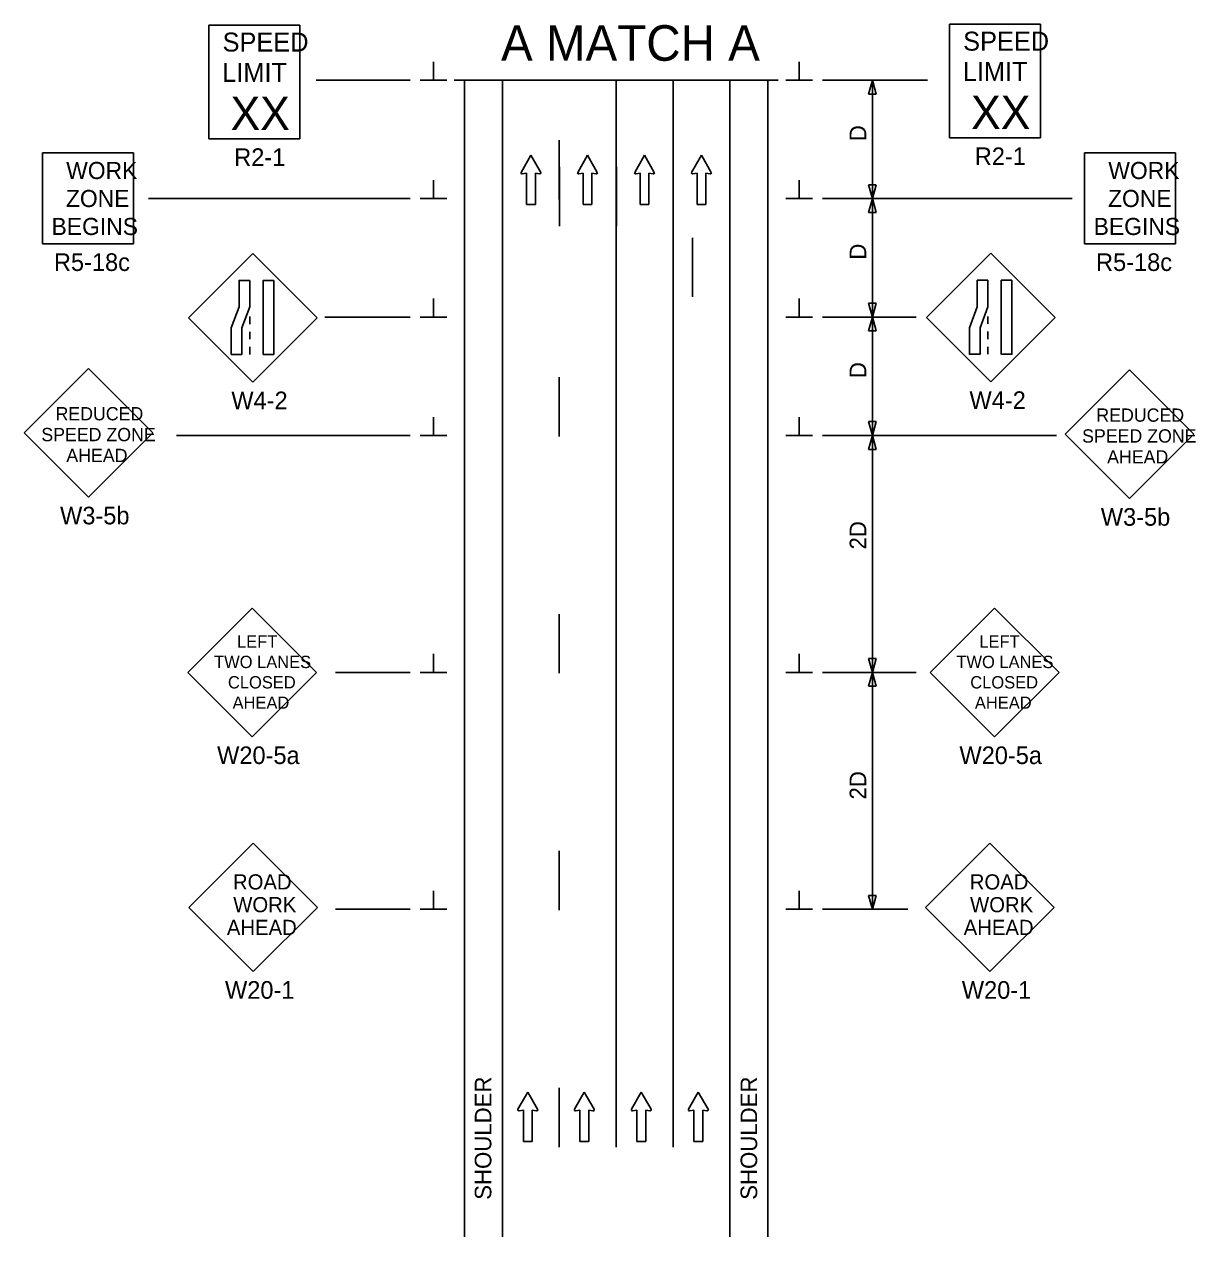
# Model space of a CAD drawing. Extents: x 16512 to 19504, y 5761 to 6984.
# Drawn here: x 17851 to 18346, y 6401 to 6913 of the extents above; entities that cross this region are included whole.
import ezdxf

# ---------------------------------------------------------------- set-up
doc = ezdxf.new("R2010")
doc.units = 0
for name, color, linetype in [('ALI_LEGAL_EX', 7, 'Continuous'), ('MT_SCRATCH_LEVEL_E', 7, 'Continuous'), ('PAVT_EDGE_EX', 7, 'Continuous'), ('TRAFFIC_SIGNS_PR', 7, 'Continuous'), ('TYPICAL_TEXT_DIMEN_PR', 7, 'Continuous')]:
    doc.layers.add(name, color=color, linetype=linetype)

msp = doc.modelspace()

# ---------------------------------------------------------------- linework, layer by layer
at = {"layer": 'ALI_LEGAL_EX'}
for p, q in [((18101.18, 6438.7), (18101.18, 6889.05)), ((18125.18, 6438.7), (18125.18, 6889.05))]:
    msp.add_line(p, q, dxfattribs=at)
for points in [[(18077.18, 6838.7), (18077.18, 6863.7)], [(18101.18, 6838.7), (18101.18, 6863.7)], [(18125.18, 6838.7), (18125.18, 6863.7)], [(18077.28, 6852.4), (18077.28, 6827.4)], [(18101.28, 6852.4), (18101.28, 6827.4)], [(18133.42, 6822.52), (18133.42, 6797.52)], [(18077.18, 6738.7), (18077.18, 6763.7)], [(18101.18, 6738.7), (18101.18, 6763.7)], [(18125.18, 6738.7), (18125.18, 6763.7)], [(18077.18, 6638.7), (18077.18, 6663.7)], [(18101.18, 6638.7), (18101.18, 6663.7)], [(18125.18, 6638.7), (18125.18, 6663.7)], [(18077.18, 6538.7), (18077.18, 6563.7)], [(18101.18, 6538.7), (18101.18, 6563.7)], [(18125.18, 6538.7), (18125.18, 6563.7)], [(18077.18, 6438.7), (18077.18, 6463.7)], [(18101.18, 6438.7), (18101.18, 6463.7)], [(18125.18, 6438.7), (18125.18, 6463.7)]]:
    msp.add_lwpolyline(points, dxfattribs=at)
at = {"layer": 'MT_SCRATCH_LEVEL_E'}
for p, q in [((18065.19, 6857.36), (18061.08, 6850.12)), ((18069.34, 6850.12), (18065.19, 6857.36)), ((18089.05, 6857.36), (18084.94, 6850.12)), ((18093.19, 6850.12), (18089.05, 6857.36)), ((18113.1, 6857.36), (18108.99, 6850.12)), ((18117.25, 6850.12), (18113.1, 6857.36)), ((18137.15, 6857.36), (18133.04, 6850.12)), ((18137.15, 6857.36), (18133.04, 6850.12)), ((18141.3, 6850.12), (18137.15, 6857.36)), ((18141.3, 6850.12), (18137.15, 6857.36)), ((18061.57, 6849.44), (18063.34, 6849.75)), ((18063.34, 6849.75), (18063.34, 6836.5)), ((18067.08, 6836.5), (18067.08, 6849.75)), ((18067.08, 6849.75), (18068.86, 6849.44)), ((18085.42, 6849.44), (18087.19, 6849.75)), ((18087.19, 6849.75), (18087.19, 6836.5)), ((18090.94, 6836.5), (18090.94, 6849.75)), ((18090.94, 6849.75), (18092.71, 6849.44)), ((18109.47, 6849.44), (18111.25, 6849.75)), ((18111.25, 6849.75), (18111.25, 6836.5)), ((18114.99, 6836.5), (18114.99, 6849.75)), ((18114.99, 6849.75), (18116.77, 6849.44)), ((18133.52, 6849.44), (18135.3, 6849.76)), ((18133.52, 6849.44), (18135.3, 6849.76)), ((18135.3, 6849.76), (18135.3, 6836.5)), ((18135.3, 6849.76), (18135.3, 6836.5)), ((18139.04, 6836.5), (18139.04, 6849.76)), ((18139.04, 6849.76), (18140.82, 6849.44)), ((18139.04, 6836.5), (18139.04, 6849.76)), ((18139.04, 6849.76), (18140.82, 6849.44)), ((18063.34, 6836.5), (18067.08, 6836.5)), ((18087.19, 6836.5), (18090.94, 6836.5)), ((18111.25, 6836.5), (18114.99, 6836.5)), ((18135.3, 6836.5), (18139.04, 6836.5)), ((18135.3, 6836.5), (18139.04, 6836.5)), ((18063.86, 6461.9), (18059.75, 6454.66)), ((18068, 6454.66), (18063.86, 6461.9)), ((18087.71, 6461.9), (18083.6, 6454.66)), ((18091.86, 6454.66), (18087.71, 6461.9)), ((18111.76, 6461.9), (18107.65, 6454.66)), ((18115.91, 6454.66), (18111.76, 6461.9)), ((18135.81, 6461.9), (18131.7, 6454.66)), ((18135.81, 6461.9), (18131.7, 6454.66)), ((18139.96, 6454.66), (18135.81, 6461.9)), ((18139.96, 6454.66), (18135.81, 6461.9)), ((18060.23, 6453.98), (18062.01, 6454.29)), ((18062.01, 6454.29), (18062.01, 6441.04)), ((18065.75, 6441.04), (18065.75, 6454.29)), ((18065.75, 6454.29), (18067.52, 6453.98)), ((18084.08, 6453.98), (18085.86, 6454.29)), ((18085.86, 6454.29), (18085.86, 6441.04)), ((18089.6, 6441.04), (18089.6, 6454.29)), ((18089.6, 6454.29), (18091.38, 6453.98)), ((18108.13, 6453.98), (18109.91, 6454.29)), ((18109.91, 6454.29), (18109.91, 6441.04)), ((18113.65, 6441.04), (18113.65, 6454.29)), ((18113.65, 6454.29), (18115.43, 6453.98)), ((18132.19, 6453.98), (18133.96, 6454.29)), ((18132.19, 6453.98), (18133.96, 6454.29)), ((18133.96, 6454.29), (18133.96, 6441.04)), ((18133.96, 6454.29), (18133.96, 6441.04)), ((18137.7, 6441.04), (18137.7, 6454.29)), ((18137.7, 6454.29), (18139.48, 6453.98)), ((18137.7, 6441.04), (18137.7, 6454.29)), ((18137.7, 6454.29), (18139.48, 6453.98)), ((18062.01, 6441.04), (18065.75, 6441.04)), ((18085.86, 6441.04), (18089.6, 6441.04)), ((18109.91, 6441.04), (18113.65, 6441.04)), ((18133.96, 6441.04), (18137.7, 6441.04)), ((18133.96, 6441.04), (18137.7, 6441.04))]:
    msp.add_line(p, q, dxfattribs=at)
for centre, start, end in [((18061.49, 6849.9), 150.4248, 279.9638), ((18068.93, 6849.9), 260.0362, 29.7731), ((18085.34, 6849.9), 150.4248, 279.9638), ((18092.78, 6849.9), 260.0362, 29.7731), ((18109.4, 6849.9), 150.4248, 279.9638), ((18116.84, 6849.9), 260.0362, 29.7731), ((18133.45, 6849.9), 150.4248, 279.9638), ((18133.45, 6849.9), 150.4248, 279.9638), ((18140.89, 6849.9), 260.0362, 29.7731), ((18140.89, 6849.9), 260.0362, 29.7731), ((18060.15, 6454.44), 150.4248, 279.9638), ((18067.6, 6454.44), 260.0362, 29.7731), ((18084.01, 6454.44), 150.4248, 279.9638), ((18091.45, 6454.44), 260.0362, 29.7731), ((18108.06, 6454.44), 150.4248, 279.9638), ((18115.5, 6454.44), 260.0362, 29.7731), ((18132.11, 6454.44), 150.4248, 279.9638), ((18132.11, 6454.44), 150.4248, 279.9638), ((18139.55, 6454.44), 260.0362, 29.7731), ((18139.55, 6454.44), 260.0362, 29.7731)]:
    msp.add_arc(centre, 0.463, start, end, dxfattribs=at)
at = {"layer": 'PAVT_EDGE_EX'}
for p, q in [((18037.18, 6889.05), (18037.18, 6400.84)), ((18053.18, 6889.05), (18053.18, 6400.84)), ((18149.18, 6889.05), (18149.18, 6400.84)), ((18165.18, 6889.05), (18165.18, 6400.84))]:
    msp.add_line(p, q, dxfattribs=at)
at = {"layer": 'TRAFFIC_SIGNS_PR'}
for p, q in [((17929.34, 6912.26), (17967.74, 6912.26)), ((17929.34, 6864.26), (17929.34, 6912.26)), ((17967.74, 6864.26), (17967.74, 6912.26)), ((18241.83, 6912.64), (18280.23, 6912.64)), ((18241.83, 6864.64), (18241.83, 6912.64)), ((18280.23, 6864.64), (18280.23, 6912.64)), ((17929.34, 6864.26), (17967.74, 6864.26)), ((18241.83, 6864.64), (18280.23, 6864.64)), ((17859.12, 6819.94), (17859.12, 6858.34)), ((17859.12, 6858.34), (17897.52, 6858.34)), ((17897.52, 6819.94), (17897.52, 6858.34)), ((18298.86, 6819.94), (18298.86, 6858.34)), ((18298.86, 6858.34), (18337.26, 6858.34)), ((18337.26, 6819.94), (18337.26, 6858.34)), ((17859.12, 6819.94), (17897.52, 6819.94)), ((18298.86, 6819.94), (18337.26, 6819.94)), ((17947.84, 6815.91), (17920.68, 6788.76)), ((17974.99, 6788.76), (17947.84, 6815.91)), ((18259.31, 6815.98), (18232.16, 6788.83)), ((18286.47, 6788.83), (18259.31, 6815.98)), ((17920.68, 6788.76), (17947.84, 6761.6)), ((17946.59, 6789.25), (17946.59, 6786.05)), ((17947.84, 6761.6), (17974.99, 6788.76)), ((18232.16, 6788.83), (18259.31, 6761.68)), ((18258.07, 6789.32), (18258.07, 6786.12)), ((18259.31, 6761.68), (18286.47, 6788.83)), ((17946.59, 6782.85), (17946.59, 6779.65)), ((18258.07, 6782.92), (18258.07, 6779.72)), ((17946.59, 6776.45), (17946.59, 6773.25)), ((18258.07, 6776.52), (18258.07, 6773.32)), ((17878.56, 6767.3), (17851.41, 6740.15)), ((17905.72, 6740.15), (17878.56, 6767.3)), ((18317.75, 6766.71), (18290.6, 6739.55)), ((18344.91, 6739.55), (18317.75, 6766.71)), ((17851.41, 6740.15), (17878.56, 6712.99)), ((17878.56, 6712.99), (17905.72, 6740.15)), ((18290.6, 6739.55), (18317.75, 6712.4)), ((18317.75, 6712.4), (18344.91, 6739.55)), ((17947.65, 6666.1), (17920.5, 6638.95)), ((17974.8, 6638.95), (17947.65, 6666.1)), ((18260.89, 6666.1), (18233.74, 6638.95)), ((18288.05, 6638.95), (18260.89, 6666.1)), ((17920.5, 6638.95), (17947.65, 6611.8)), ((17947.65, 6611.8), (17974.8, 6638.95)), ((18233.74, 6638.95), (18260.89, 6611.8)), ((18260.89, 6611.8), (18288.05, 6638.95)), ((17947.95, 6567.04), (17920.8, 6539.89)), ((17975.1, 6539.89), (17947.95, 6567.04)), ((18258.87, 6567.04), (18231.72, 6539.89)), ((18286.02, 6539.89), (18258.87, 6567.04)), ((17920.8, 6539.89), (17947.95, 6512.74)), ((17947.95, 6512.74), (17975.1, 6539.89)), ((18231.72, 6539.89), (18258.87, 6512.74)), ((18258.87, 6512.74), (18286.02, 6539.89))]:
    msp.add_line(p, q, dxfattribs=at)
for points in [[(17946.59, 6804.49), (17946.59, 6793.31), (17943.24, 6784.43), (17943.24, 6773.25), (17938.75, 6773.25), (17938.75, 6784.43), (17942.09, 6793.31), (17942.09, 6804.49)], [(17956.72, 6804.49), (17956.72, 6773.25), (17952.23, 6773.25), (17952.23, 6804.49)], [(18258.07, 6804.57), (18258.07, 6793.38), (18254.72, 6784.5), (18254.72, 6773.32), (18250.23, 6773.32), (18250.23, 6784.5), (18253.57, 6793.38), (18253.57, 6804.57)], [(18268.2, 6804.57), (18268.2, 6773.32), (18263.71, 6773.32), (18263.71, 6804.57)]]:
    msp.add_lwpolyline(points, close=True, dxfattribs=at)
at = {"layer": 'TYPICAL_TEXT_DIMEN_PR'}
for p, q in [((18024.15, 6889.05), (18024.15, 6896.83)), ((18178.4, 6889.05), (18178.4, 6896.83)), ((17974.63, 6889.05), (18014.28, 6889.05)), ((18018.53, 6889.05), (18029.78, 6889.05)), ((18032.85, 6889.05), (18169.5, 6889.05)), ((18184.03, 6889.05), (18172.78, 6889.05)), ((18188.28, 6889.05), (18232.62, 6889.05)), ((18207.71, 6883.19), (18209.28, 6889.05)), ((18209.28, 6889.05), (18209.28, 6839.05)), ((18209.28, 6889.05), (18210.85, 6883.19)), ((18209.28, 6883.19), (18207.71, 6883.19)), ((18210.85, 6883.19), (18209.28, 6883.19)), ((18024.15, 6839.05), (18024.15, 6846.83)), ((18178.4, 6839.05), (18178.4, 6846.83)), ((18209.28, 6839.05), (18207.71, 6844.91)), ((18207.71, 6844.91), (18209.28, 6844.91)), ((18209.28, 6844.91), (18210.85, 6844.91)), ((18210.85, 6844.91), (18209.28, 6839.05)), ((18014.28, 6839.05), (17903.81, 6839.05)), ((18018.53, 6839.05), (18029.78, 6839.05)), ((18184.03, 6839.05), (18172.78, 6839.05)), ((18188.28, 6839.05), (18293.55, 6839.05)), ((18207.71, 6833.19), (18209.28, 6839.05)), ((18209.28, 6839.05), (18210.85, 6833.19)), ((18209.28, 6839.05), (18209.28, 6789.05)), ((18209.28, 6833.19), (18207.71, 6833.19)), ((18210.85, 6833.19), (18209.28, 6833.19)), ((18024.15, 6789.05), (18024.15, 6796.83)), ((18178.4, 6789.05), (18178.4, 6796.83)), ((18209.28, 6789.05), (18207.71, 6794.91)), ((18207.71, 6794.91), (18209.28, 6794.91)), ((18209.28, 6794.91), (18210.85, 6794.91)), ((18210.85, 6794.91), (18209.28, 6789.05)), ((18014.28, 6789.05), (17978.28, 6789.05)), ((18018.53, 6789.05), (18029.78, 6789.05)), ((18184.03, 6789.05), (18172.78, 6789.05)), ((18188.28, 6789.05), (18227.73, 6789.05)), ((18207.71, 6783.19), (18209.28, 6789.05)), ((18209.28, 6789.05), (18209.28, 6739.05)), ((18209.28, 6789.05), (18210.85, 6783.19)), ((18209.28, 6783.19), (18207.71, 6783.19)), ((18210.85, 6783.19), (18209.28, 6783.19)), ((18024.15, 6739.05), (18024.15, 6746.83)), ((18178.4, 6739.05), (18178.4, 6746.83)), ((18209.28, 6739.05), (18207.71, 6744.91)), ((18207.71, 6744.91), (18209.28, 6744.91)), ((18209.28, 6744.91), (18210.85, 6744.91)), ((18210.85, 6744.91), (18209.28, 6739.05)), ((17915.6, 6739.05), (18014.28, 6739.05)), ((18018.53, 6739.05), (18029.78, 6739.05)), ((18184.03, 6739.05), (18172.78, 6739.05)), ((18188.28, 6739.05), (18286.96, 6739.05)), ((18207.71, 6733.19), (18209.28, 6739.05)), ((18207.71, 6733.19), (18209.28, 6739.05)), ((18209.28, 6739.05), (18209.28, 6639.05)), ((18209.28, 6739.05), (18210.85, 6733.19)), ((18209.28, 6739.05), (18210.85, 6733.19)), ((18209.28, 6739.05), (18209.28, 6639.05)), ((18209.28, 6733.19), (18207.71, 6733.19)), ((18209.28, 6733.19), (18207.71, 6733.19)), ((18210.85, 6733.19), (18209.28, 6733.19)), ((18210.85, 6733.19), (18209.28, 6733.19)), ((18024.15, 6639.05), (18024.15, 6646.83)), ((18024.15, 6639.05), (18024.15, 6646.83)), ((18178.4, 6639.05), (18178.4, 6646.83)), ((18178.4, 6639.05), (18178.4, 6646.83)), ((18209.28, 6639.05), (18207.71, 6644.91)), ((18207.71, 6644.91), (18209.28, 6644.91)), ((18209.28, 6644.91), (18210.85, 6644.91)), ((18210.85, 6644.91), (18209.28, 6639.05)), ((17982.71, 6639.05), (18014.28, 6639.05)), ((18029.78, 6639.05), (18018.53, 6639.05)), ((18029.78, 6639.05), (18018.53, 6639.05)), ((18184.03, 6639.05), (18172.78, 6639.05)), ((18184.03, 6639.05), (18172.78, 6639.05)), ((18188.28, 6639.05), (18227.73, 6639.05)), ((18188.28, 6639.05), (18214.28, 6639.05)), ((18207.71, 6633.19), (18209.28, 6639.05)), ((18209.28, 6639.05), (18209.28, 6539.05)), ((18209.28, 6639.05), (18210.85, 6633.19)), ((18209.28, 6633.19), (18207.71, 6633.19)), ((18210.85, 6633.19), (18209.28, 6633.19)), ((18024.15, 6539.05), (18024.15, 6546.83)), ((18178.4, 6539.05), (18178.4, 6546.83)), ((18209.28, 6539.05), (18207.71, 6544.91)), ((18207.71, 6544.91), (18209.28, 6544.91)), ((18209.28, 6544.91), (18210.85, 6544.91)), ((18210.85, 6544.91), (18209.28, 6539.05)), ((17982.71, 6539.05), (18014.28, 6539.05)), ((18029.78, 6539.05), (18018.53, 6539.05)), ((18184.03, 6539.05), (18172.78, 6539.05)), ((18188.28, 6539.05), (18224.28, 6539.05))]:
    msp.add_line(p, q, dxfattribs=at)

# ---------------------------------------------------------------- texts
at = {"layer": 'TRAFFIC_SIGNS_PR'}
for s, height, p in [('SPEED', 8, (18247.6, 6901.5)), ('SPEED', 8, (17935.1, 6901.12)), ('LIMIT', 8, (17934.94, 6888.32)), ('LIMIT', 8, (18247.44, 6888.7)), ('XX', 14.031, (17938.45, 6868.02)), ('XX', 14.031, (18250.94, 6868.4)), ('R2-1', 7.44, (17940.01, 6852.82)), ('R2-1', 7.44, (18252.51, 6853.2)), ('WORK', 7.217, (17869.11, 6847.3)), ('WORK', 7.217, (18308.86, 6847.3)), ('ZONE', 7.217, (17869, 6835.49)), ('ZONE', 7.217, (18308.74, 6835.49)), ('BEGINS', 7.217, (17862.93, 6823.68)), ('BEGINS', 7.217, (18302.67, 6823.68)), ('R5-18c', 7.44, (17863.93, 6808.5)), ('R5-18c', 7.44, (18303.67, 6808.5)), ('W4-2', 7.44, (17938.79, 6750.16)), ('W4-2', 7.44, (18250.27, 6750.24)), ('REDUCED', 5.6, (17864.62, 6745.45)), ('REDUCED', 5.6, (18303.81, 6744.86)), ('SPEED ZONE', 5.6, (17858.61, 6736.65)), ('SPEED ZONE', 5.6, (18297.8, 6736.06)), ('AHEAD', 5.6, (17869.17, 6727.85)), ('AHEAD', 5.6, (18308.36, 6727.26)), ('W3-5b', 7.44, (17866.52, 6701.55)), ('W3-5b', 7.44, (18305.7, 6700.96)), ('LEFT', 5.2, (17941.19, 6649.48)), ('LEFT', 5.2, (18254.43, 6649.48)), ('TWO LANES', 5.2, (17931.51, 6640.88)), ('TWO LANES', 5.2, (18244.75, 6640.88)), ('CLOSED', 5.2, (17937.36, 6632.28)), ('CLOSED', 5.2, (18250.61, 6632.28)), ('AHEAD', 5.2, (17939.31, 6623.68)), ('AHEAD', 5.2, (18252.55, 6623.68)), ('W20-5a', 7.44, (17932.79, 6600.36)), ('W20-5a', 7.44, (18246.03, 6600.36)), ('ROAD', 6.4, (17939.49, 6547.42)), ('ROAD', 6.4, (18250.41, 6547.42)), ('WORK', 6.4, (17939.6, 6537.82)), ('WORK', 6.4, (18250.52, 6537.82)), ('AHEAD', 6.4, (17936.91, 6528.22)), ('AHEAD', 6.4, (18247.83, 6528.22)), ('W20-1', 7.44, (17936.12, 6501.3)), ('W20-1', 7.44, (18247.04, 6501.3))]:
    msp.add_text(s, height=height, dxfattribs=at).set_placement(p)
at = {"layer": 'TYPICAL_TEXT_DIMEN_PR'}
msp.add_text('A MATCH A', height=15, dxfattribs=at).set_placement((18052.6, 6897.23))
for s, p in [('D', (18206.72, 6863.27)), ('D', (18206.72, 6813.27)), ('D', (18206.72, 6763.27)), ('2D', (18206.72, 6690.94)), ('2D', (18206.72, 6585.41)), ('SHOULDER', (18048.51, 6416.45)), ('SHOULDER', (18160.68, 6416.45))]:
    msp.add_text(s, height=7, rotation=90, dxfattribs=at).set_placement(p)

doc.saveas('drawing.dxf')
